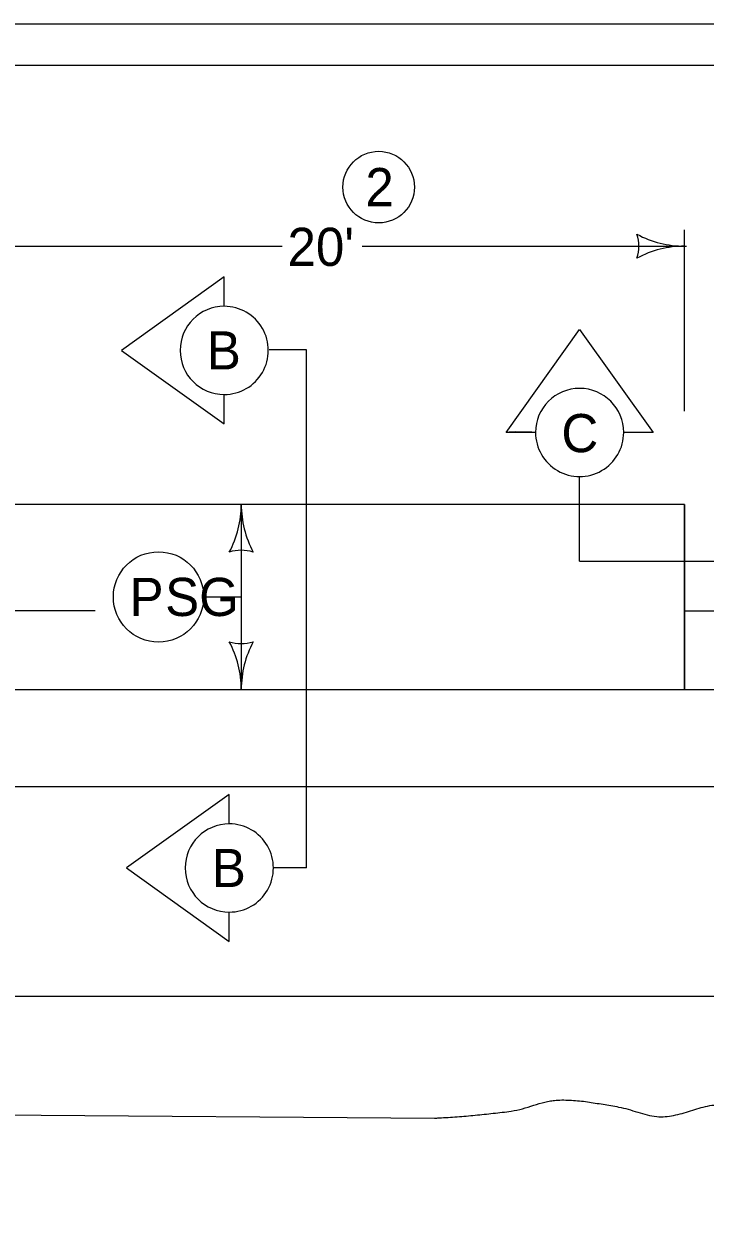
# Model space of a CAD drawing. Extents: x 10038 to 81668, y 7924 to 11018.
# Drawn here: x 11527 to 11812, y 9443 to 9944 of the extents above; entities that cross this region are included whole.
import ezdxf

# ---------------------------------------------------------------- set-up
doc = ezdxf.new("R2010")
doc.units = 0
for name, color, linetype in [('DsnShtMinorGrid05', 7, 'Continuous'), ('DsnShtMinorGrid06', 7, 'Continuous'), ('DsnShtMinorGrid09', 7, 'Continuous'), ('DsnShtMinorGrid11', 7, 'Continuous'), ('DsnShtMinorGrid13', 7, 'Continuous'), ('Level 60', 7, 'Continuous'), ('SheetBorder', 7, 'Continuous')]:
    doc.layers.add(name, color=color, linetype=linetype)

msp = doc.modelspace()

# ---------------------------------------------------------------- linework, layer by layer
at = {"layer": 'DsnShtMinorGrid05'}
for p, q in [((11803.64, 9781.65), (11803.64, 9857.67)), ((11498.9, 9850.84), (11634.9, 9850.84)), ((11668.42, 9850.84), (11804.42, 9850.84)), ((11617.73, 9742.58), (11617.73, 9665)), ((11601.97, 9703.79), (11617.73, 9703.79))]:
    msp.add_line(p, q, dxfattribs=at)
msp.add_circle((11583.04, 9703.79), 18.93, dxfattribs=at)
for centre, radius, start, end in [((11768, 9850.84), 16.42, 342.2666, 17.7333), ((11803.64, 9893.34), 42.5, 241.9275, 270), ((11803.64, 9808.34), 42.5, 90, 118.0725), ((11575.23, 9742.58), 42.5, 331.9275, 0), ((11660.23, 9742.58), 42.5, 180, 208.0725), ((11617.73, 9706.94), 16.42, 72.2666, 107.7334), ((11617.73, 9700.64), 16.42, 252.2666, 287.7333), ((11575.23, 9665), 42.5, 360, 28.0725), ((11660.23, 9665), 42.5, 151.9275, 180)]:
    msp.add_arc(centre, radius, start, end, dxfattribs=at)
at = {"layer": 'DsnShtMinorGrid06'}
msp.add_line((10150.33, 9926.71), (13246.02, 9926.71), dxfattribs=at)
at = {"layer": 'DsnShtMinorGrid09'}
msp.add_circle((11675.35, 9875.6), 15, dxfattribs=at)
at = {"layer": 'DsnShtMinorGrid11'}
for p, q in [((11556.45, 9697.98), (10524.54, 9697.98)), ((10350.4, 9536.44), (11992.44, 9536.44))]:
    msp.add_line(p, q, dxfattribs=at)
at = {"layer": 'DsnShtMinorGrid13'}
for p, q in [((11645.15, 9807.45), (11629.38, 9807.45)), ((11645.15, 9590.16), (11645.15, 9807.45)), ((11759.59, 9718.81), (11759.59, 9754.26)), ((11759.59, 9718.81), (11847.69, 9718.81)), ((11645.15, 9590.16), (11631.2, 9590.16))]:
    msp.add_line(p, q, dxfattribs=at)
for points in [[(11610.59, 9825.63), (11610.59, 9837.95), (11567.46, 9807.14), (11610.59, 9776.33), (11610.59, 9788.66)], [(11741.1, 9772.74), (11728.78, 9772.74), (11759.59, 9815.87), (11790.4, 9772.74), (11778.07, 9772.74)], [(11612.71, 9608.65), (11612.71, 9620.97), (11569.58, 9590.16), (11612.71, 9559.35), (11612.71, 9571.68)]]:
    msp.add_lwpolyline(points, dxfattribs=at)
for centre, start, end in [((11610.59, 9807.14), 90.0008, 269.9992), ((11610.59, 9807.14), 269.9992, 90.0008), ((11759.59, 9772.74), 0.0008, 179.9992), ((11759.59, 9772.74), 179.9992, 0.0008), ((11612.71, 9590.16), 90.0008, 269.9992), ((11612.71, 9590.16), 269.9992, 90.0008)]:
    msp.add_arc(centre, 18.49, start, end, dxfattribs=at)
at = {"layer": 'Level 60'}
for p, q in [((11739.5, 9772.89), (11730.26, 9772.98)), ((11739.5, 9772.89), (11732.89, 9772.95)), ((11803.64, 9742.58), (11498.9, 9742.58)), ((11803.64, 9742.58), (11498.9, 9742.58)), ((11803.64, 9742.58), (11803.64, 9665)), ((11803.64, 9665), (11803.64, 9742.58)), ((11803.64, 9697.98), (11981.52, 9697.98)), ((10345.8, 9665), (11993.27, 9665)), ((11498.9, 9665), (11803.64, 9665)), ((10367.01, 9624.35), (11980.8, 9624.35)), ((11369.49, 9487.72), (11698.69, 9485.27))]:
    msp.add_line(p, q, dxfattribs=at)
msp.add_circle((11583.04, 9703.79), 18.93, dxfattribs=at)
msp.add_spline([(11698.69, 9485.27), (11700.69, 9485.38), (11708.26, 9485.86), (11715.83, 9486.52), (11723.38, 9487.32), (11730.91, 9488.23), (11735.66, 9489.23), (11740.34, 9490.67), (11745.01, 9492.03), (11747.36, 9492.52), (11749.73, 9492.79), (11756.26, 9492.78), (11762.86, 9492.12), (11769.44, 9491.08), (11775.96, 9489.94), (11779.97, 9489), (11783.94, 9487.8), (11787.92, 9486.67), (11791.93, 9485.95), (11795.47, 9485.92), (11799.02, 9486.42), (11806.13, 9488.35), (11813.26, 9490.36), (11820.44, 9491.08), (11834.97, 9490.11), (11849.52, 9488.8), (11856.24, 9487.98), (11862.94, 9486.99), (11869.64, 9486.05), (11876.32, 9485.38), (11882.07, 9485.94), (11887.75, 9487.77), (11893.41, 9489.82), (11899.13, 9491.08), (11906.63, 9491.59), (11914.23, 9491.72), (11925.61, 9491.02), (11929.35, 9490.51), (11936.37, 9488.69), (11943.26, 9486.12), (11950.18, 9483.75), (11957.29, 9482.52), (11978.4, 9481.52)], degree=3, dxfattribs=at)
at = {"layer": 'SheetBorder'}
msp.add_lwpolyline([(10132.52, 9944.02), (13267.53, 9944.02), (13267.53, 7924.02), (10132.52, 7924.02)], close=True, dxfattribs=at)

# ---------------------------------------------------------------- texts
at = {"layer": 'DsnShtMinorGrid05'}
for s, p in [("20'", (11637.14, 9842.56)), ('P', (11570.91, 9695.79)), ('SG', (11585.82, 9695.79))]:
    msp.add_text(s, height=16, dxfattribs=at).set_placement(p)
at = {"layer": 'DsnShtMinorGrid09'}
msp.add_text('2', height=16, dxfattribs=at).set_placement((11669.77, 9867.6))
at = {"layer": 'DsnShtMinorGrid13'}
for s, p in [('B', (11603.31, 9799.14)), ('C', (11751.96, 9764.47)), ('B', (11605.41, 9582.16))]:
    msp.add_text(s, height=16, dxfattribs=at).set_placement(p)

doc.saveas('drawing.dxf')
